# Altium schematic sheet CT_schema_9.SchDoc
size 147 x 119 mm
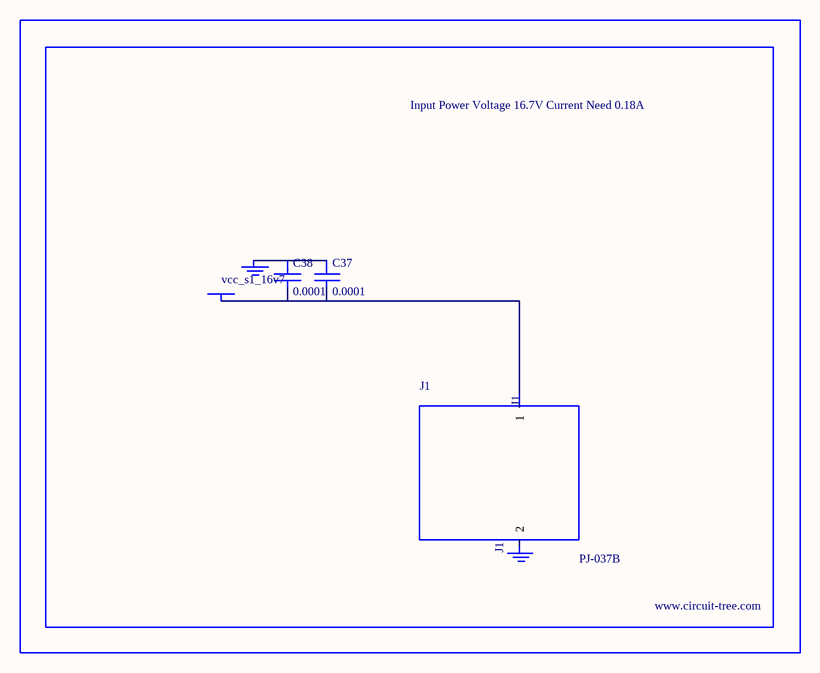
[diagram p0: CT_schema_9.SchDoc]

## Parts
BORDER8  (no value)
C37  0.0001  [EXV-9H]
C38  0.0001  [EXV-9H]
GND_INSTANCE_8_0  (no value)
GND_INSTANCE_8_1  (no value)
J1  PJ-037B  [PJ-037B_PACKAGE]
POWER_INSTANCE_8_0  vcc_s1_16v7

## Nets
NetC37_1: C37.1 C38.1 GND_INSTANCE_8_0.0(GND)
NetC37_2: C37.2 C38.2 J1.1 POWER_INSTANCE_8_0.0(PWR)

Not connected (* = marked no-connect by the designer): GND_INSTANCE_8_1 0(GND); J1 2

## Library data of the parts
BORDER8 = BORDER_PAGE8
C37 C38 = EDK107M035A9HAA
GND_INSTANCE_8_0 GND_INSTANCE_8_1 = GND
POWER_INSTANCE_8_0 = PWR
